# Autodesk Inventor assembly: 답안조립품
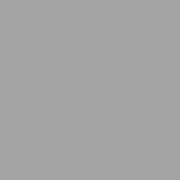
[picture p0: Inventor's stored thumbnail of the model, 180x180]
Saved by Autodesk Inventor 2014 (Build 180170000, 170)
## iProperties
Created: 2015-06
Part Number: 답안조립품
Document SubType Name: Assembly
Designer: MYHOME
Author: MYHOME
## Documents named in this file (1)
- C:\Documents and Settings\MYHOME\바탕 화면\450631V1033\답안조립품.iam
